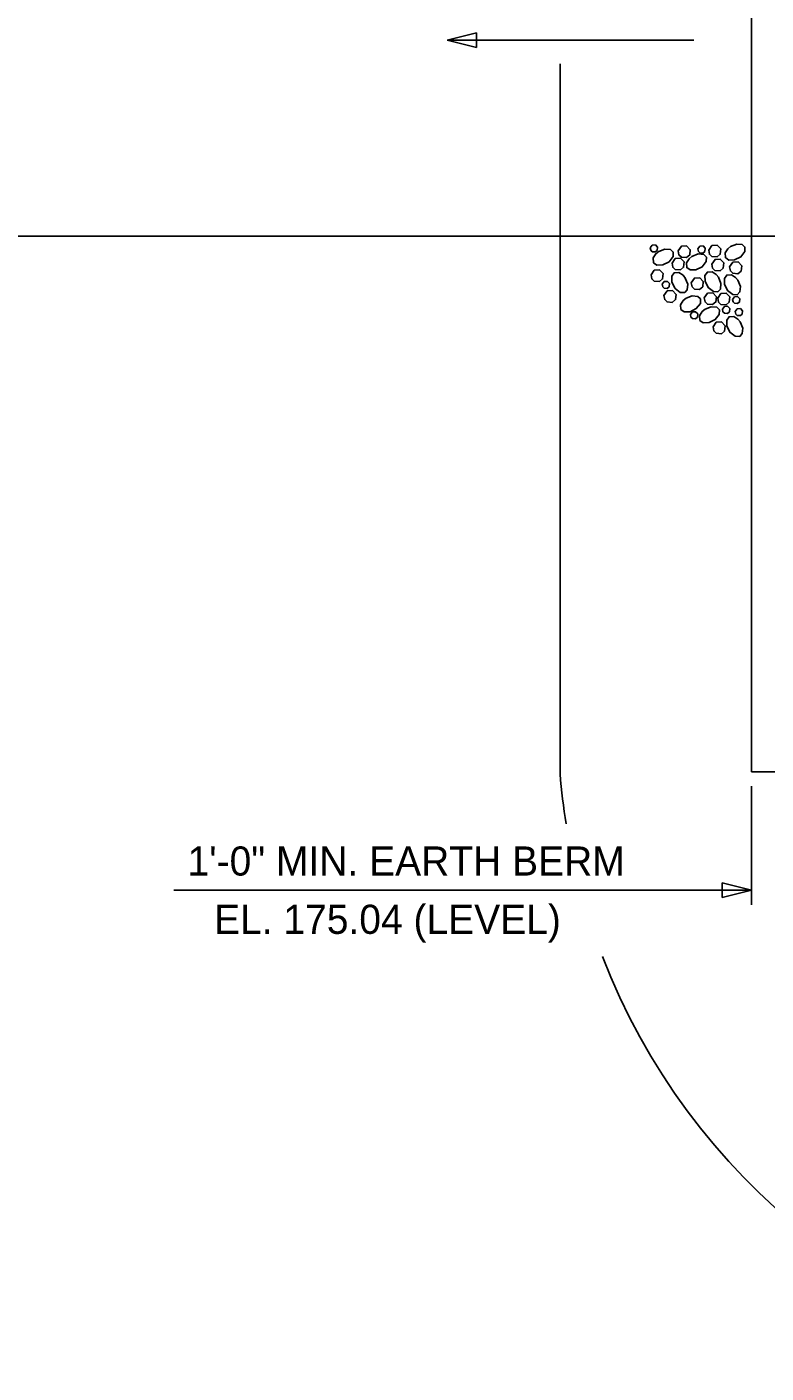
# Model space of a CAD drawing. Extents: x 0 to 265, y -200 to 22.
# Drawn here: x 119.9 to 145.25, y -97.36 to -51.17 of the extents above; entities that cross this region are included whole.
import ezdxf

# ---------------------------------------------------------------- set-up
doc = ezdxf.new("R2010")
doc.units = 0
for name, color, linetype in [('Arrowhead Terminators CELL', 7, 'Continuous'), ('Auto Dimensioning', 7, 'Continuous'), ('Dimension Lines', 7, 'Continuous'), ('Mis -L- Lines', 7, 'Continuous'), ('Mis Object Lines', 7, 'Continuous'), ('Miscellaneous Lines CELL', 7, 'Continuous'), ('Sub End Bent Cap Lines CELL', 7, 'Continuous'), ('Sup Concrete Girder Lines', 7, 'Continuous'), ('Text', 7, 'Continuous')]:
    doc.layers.add(name, color=color, linetype=linetype)

# ---------------------------------------------------------------- blocks, each defined once
blk = doc.blocks.new('AH')
at = {"layer": 'Sub End Bent Cap Lines CELL'}
blk.add_lwpolyline([(0, 0), (-1.25, 0.312), (-1.25, -0.312)], close=True, dxfattribs=at)

msp = doc.modelspace()

# ---------------------------------------------------------------- linework, layer by layer
at = {"layer": 'Arrowhead Terminators CELL'}
msp.add_lwpolyline([(134.31, -51.624), (135.31, -51.874), (135.31, -51.374)], close=True, dxfattribs=at)
at = {"layer": 'Auto Dimensioning'}
for p, q in [((144.746, -77.222), (144.746, -81.287)), ((124.935, -80.787), (144.746, -80.787))]:
    msp.add_line(p, q, dxfattribs=at)
at = {"layer": 'Dimension Lines'}
msp.add_line((134.31, -51.624), (142.774, -51.624), dxfattribs=at)
at = {"layer": 'Mis -L- Lines'}
msp.add_line((49.574, -58.349), (176.83, -58.349), dxfattribs=at)
at = {"layer": 'Mis Object Lines'}
for p, q in [((144.746, -39.933), (144.746, -76.722)), ((144.746, -76.722), (159.366, -76.722))]:
    msp.add_line(p, q, dxfattribs=at)
at = {"layer": 'Miscellaneous Lines CELL'}
for points in [[(141.276, -58.75), (141.344, -58.654), (141.451, -58.648), (141.526, -58.726), (141.515, -58.834), (141.448, -58.889), (141.342, -58.881), (141.293, -58.833), (141.276, -58.75)], [(143.278, -58.828), (143.39, -58.669), (143.569, -58.658), (143.693, -58.787), (143.675, -58.968), (143.564, -59.06), (143.388, -59.047), (143.305, -58.967), (143.278, -58.828)], [(144.029, -58.701), (144.239, -58.618), (144.432, -58.634), (144.523, -58.721), (144.52, -58.877), (144.381, -59.055), (144.167, -59.162), (143.964, -59.166), (143.851, -59.085), (143.84, -58.924), (143.932, -58.78), (144.038, -58.695)], [(141.567, -58.873), (141.776, -58.79), (141.969, -58.806), (142.06, -58.893), (142.057, -59.049), (141.919, -59.227), (141.704, -59.334), (141.502, -59.338), (141.388, -59.257), (141.377, -59.096), (141.469, -58.952), (141.575, -58.867)], [(142.02, -59.274), (142.132, -59.115), (142.311, -59.104), (142.435, -59.233), (142.417, -59.414), (142.306, -59.506), (142.13, -59.493), (142.047, -59.412), (142.02, -59.274)], [(142.231, -58.852), (142.343, -58.693), (142.521, -58.683), (142.646, -58.812), (142.628, -58.992), (142.517, -59.084), (142.341, -59.071), (142.258, -58.991), (142.231, -58.852)], [(142.705, -59.042), (142.915, -58.959), (143.108, -58.976), (143.199, -59.063), (143.196, -59.219), (143.057, -59.397), (142.843, -59.504), (142.64, -59.507), (142.526, -59.426), (142.516, -59.265), (142.608, -59.121), (142.714, -59.037)], [(142.91, -58.787), (142.978, -58.691), (143.085, -58.685), (143.16, -58.762), (143.149, -58.871), (143.082, -58.926), (142.976, -58.918), (142.927, -58.87), (142.91, -58.787)], [(141.301, -59.674), (141.413, -59.514), (141.592, -59.504), (141.717, -59.633), (141.699, -59.814), (141.588, -59.906), (141.411, -59.893), (141.328, -59.812), (141.301, -59.674)], [(143.616, -59.759), (143.699, -59.969), (143.683, -60.161), (143.596, -60.253), (143.439, -60.25), (143.262, -60.111), (143.155, -59.897), (143.151, -59.694), (143.232, -59.58), (143.393, -59.57), (143.537, -59.662), (143.622, -59.768)], [(143.383, -59.305), (143.495, -59.146), (143.674, -59.136), (143.798, -59.265), (143.78, -59.445), (143.67, -59.537), (143.493, -59.524), (143.41, -59.444), (143.383, -59.305)], [(143.996, -59.403), (144.108, -59.243), (144.287, -59.233), (144.411, -59.362), (144.393, -59.543), (144.282, -59.635), (144.106, -59.622), (144.023, -59.541), (143.996, -59.403)], [(141.686, -60), (141.753, -59.905), (141.861, -59.899), (141.935, -59.976), (141.925, -60.084), (141.858, -60.14), (141.752, -60.132), (141.702, -60.084), (141.686, -60)], [(142.477, -59.786), (142.561, -59.996), (142.544, -60.189), (142.457, -60.28), (142.301, -60.277), (142.123, -60.138), (142.016, -59.924), (142.012, -59.721), (142.093, -59.607), (142.254, -59.597), (142.398, -59.689), (142.483, -59.795)], [(142.679, -59.945), (142.791, -59.786), (142.97, -59.775), (143.094, -59.904), (143.076, -60.085), (142.965, -60.177), (142.789, -60.164), (142.706, -60.084), (142.679, -59.945)], [(144.28, -59.861), (144.364, -60.071), (144.347, -60.263), (144.26, -60.355), (144.104, -60.352), (143.926, -60.213), (143.819, -59.998), (143.815, -59.796), (143.896, -59.682), (144.057, -59.671), (144.201, -59.764), (144.286, -59.869)], [(141.743, -60.386), (141.855, -60.226), (142.034, -60.216), (142.159, -60.345), (142.141, -60.526), (142.03, -60.618), (141.853, -60.605), (141.77, -60.524), (141.743, -60.386)], [(142.502, -60.479), (142.712, -60.396), (142.904, -60.413), (142.996, -60.5), (142.993, -60.656), (142.854, -60.834), (142.639, -60.941), (142.437, -60.944), (142.323, -60.863), (142.312, -60.702), (142.405, -60.558), (142.511, -60.474)], [(143.127, -60.465), (143.239, -60.305), (143.418, -60.295), (143.542, -60.424), (143.524, -60.605), (143.414, -60.697), (143.237, -60.684), (143.154, -60.603), (143.127, -60.465)], [(143.588, -60.471), (143.7, -60.312), (143.879, -60.302), (144.003, -60.431), (143.985, -60.611), (143.875, -60.703), (143.698, -60.69), (143.615, -60.61), (143.588, -60.471)], [(144.098, -60.521), (144.165, -60.425), (144.272, -60.419), (144.347, -60.496), (144.336, -60.605), (144.27, -60.66), (144.164, -60.652), (144.114, -60.604), (144.098, -60.521)], [(142.653, -61.041), (142.72, -60.945), (142.828, -60.939), (142.902, -61.016), (142.891, -61.125), (142.825, -61.18), (142.719, -61.172), (142.669, -61.124), (142.653, -61.041)], [(143.152, -60.854), (143.362, -60.771), (143.555, -60.787), (143.646, -60.874), (143.643, -61.03), (143.504, -61.208), (143.29, -61.315), (143.087, -61.319), (142.973, -61.238), (142.963, -61.077), (143.055, -60.933), (143.161, -60.848)], [(143.751, -60.857), (143.818, -60.761), (143.926, -60.755), (144, -60.832), (143.989, -60.941), (143.923, -60.996), (143.817, -60.988), (143.767, -60.94), (143.751, -60.857)], [(144.192, -60.936), (144.26, -60.84), (144.367, -60.834), (144.442, -60.911), (144.431, -61.02), (144.364, -61.075), (144.258, -61.067), (144.209, -61.019), (144.192, -60.936)], [(143.427, -61.462), (143.539, -61.303), (143.718, -61.292), (143.842, -61.421), (143.824, -61.602), (143.714, -61.694), (143.537, -61.681), (143.454, -61.6), (143.427, -61.462)], [(144.362, -61.291), (144.445, -61.501), (144.428, -61.693), (144.341, -61.785), (144.185, -61.782), (144.007, -61.643), (143.9, -61.428), (143.897, -61.226), (143.977, -61.112), (144.139, -61.101), (144.283, -61.194), (144.367, -61.3)]]:
    msp.add_lwpolyline(points, dxfattribs=at)
at = {"layer": 'Sup Concrete Girder Lines'}
for p, q in [((138.179, -52.431), (138.179, -53.609)), ((138.179, -53.609), (138.179, -76.797))]:
    msp.add_line(p, q, dxfattribs=at)
for start, end in [(184.9278, 189.284), (201.1777, 261.7748)]:
    msp.add_arc((160.842, -74.843), 22.747, start, end, dxfattribs=at)

# ---------------------------------------------------------------- block references
at = {"layer": 'Auto Dimensioning', "xscale": 0.8, "yscale": 0.8000000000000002}
msp.add_blockref('AH', (144.746, -80.787), dxfattribs=at)

# ---------------------------------------------------------------- texts
at = {"layer": 'Text'}
for s, p in [('1\'-0" MIN. EARTH BERM', (125.403, -80.287)), ('EL. 175.04 (LEVEL)', (126.314, -82.287))]:
    msp.add_text(s, height=1, dxfattribs=at).set_placement(p)

doc.saveas('drawing.dxf')
